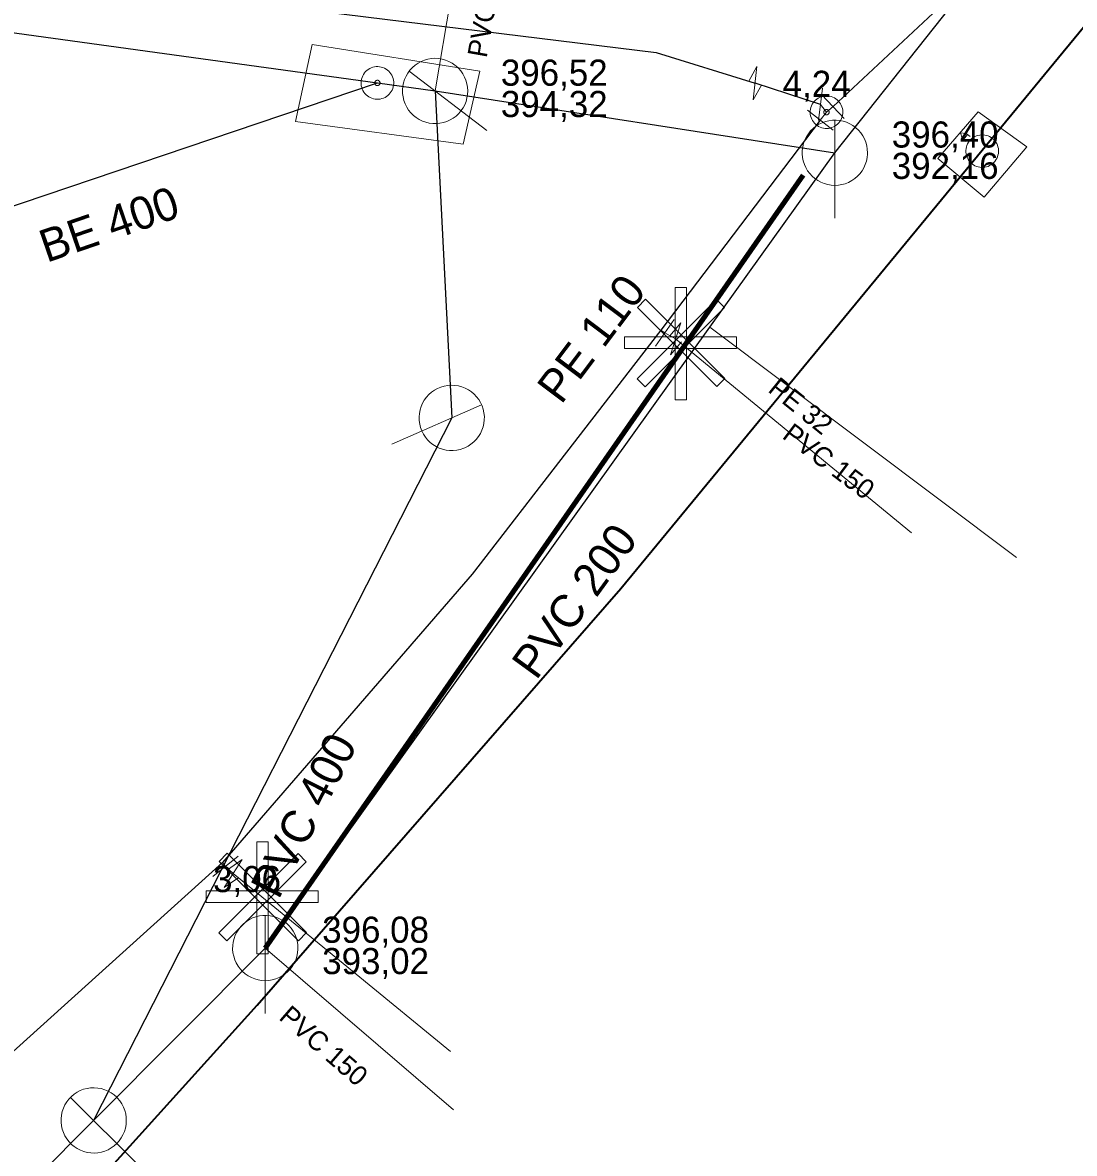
# Model space of a CAD drawing. Extents: x -809028 to -807737, y -990545 to -989489.
# Drawn here: x -808650.26 to -808618.05, y -990038.3 to -990003.67 of the extents above; entities that cross this region are included whole.
import ezdxf

# ---------------------------------------------------------------- set-up
doc = ezdxf.new("R2010")
doc.units = 0
doc.header["$LTSCALE"] = 0.32
for name, color, linetype, lineweight in [('1', 7, 'Continuous', 13), ('11', 7, 'Continuous', 13), ('12', 7, 'Continuous', 13), ('13', 7, 'Continuous', 13), ('14', 7, 'Continuous', 25), ('17', 7, 'Continuous', 25), ('2', 7, 'Continuous', 13), ('22', 7, 'Continuous', 13), ('23', 7, 'Continuous', 13), ('31', 7, 'Continuous', 13), ('34', 7, 'Continuous', 13), ('47', 7, 'Continuous', 13)]:
    doc.layers.add(name, color=color, linetype=linetype, lineweight=lineweight)

msp = doc.modelspace()

# ---------------------------------------------------------------- linework, layer by layer
at = {"layer": '1'}
msp.add_lwpolyline([(-808641.395, -990004.333), (-808641.909, -990006.699), (-808636.769, -990007.385), (-808636.254, -990005.157)], close=True, dxfattribs=at)
at = {"layer": '11'}
for p, q in [((-808636.524, -989999.172), (-808637.629, -990005.76)), ((-808619.815, -990020.044), (-808629.213, -990012.999)), ((-808637.065, -990036.969), (-808642.829, -990032.01))]:
    msp.add_line(p, q, dxfattribs=at)
at = {"layer": '12'}
for points in [[(-808630.277, -990011.784), (-808629.926, -990011.784), (-808629.926, -990015.219), (-808630.277, -990015.219)], [(-808629.011, -990012.148), (-808628.762, -990012.396), (-808631.191, -990014.825), (-808631.438, -990014.577)], [(-808631.429, -990012.387), (-808631.183, -990012.139), (-808628.754, -990014.568), (-808629, -990014.816)], [(-808628.392, -990013.293), (-808628.392, -990013.643), (-808631.828, -990013.643), (-808631.828, -990013.293)], [(-808643.093, -990028.753), (-808642.743, -990028.753), (-808642.743, -990032.188), (-808643.093, -990032.188)], [(-808641.827, -990029.117), (-808641.579, -990029.365), (-808644.008, -990031.794), (-808644.255, -990031.546)], [(-808644.246, -990029.356), (-808643.999, -990029.108), (-808641.57, -990031.537), (-808641.817, -990031.785)], [(-808641.209, -990030.262), (-808641.209, -990030.612), (-808644.644, -990030.612), (-808644.644, -990030.262)]]:
    msp.add_lwpolyline(points, close=True, dxfattribs=at)
at = {"layer": '13'}
msp.add_line((-808644.048, -990029.511), (-808643.817, -990029.732), dxfattribs=at)
for points in [[(-808630.591, -990013.17), (-808630.26, -990013.352), (-808623.037, -990019.291)], [(-808643.817, -990029.732), (-808642.936, -990030.438), (-808637.155, -990035.181)]]:
    msp.add_lwpolyline(points, dxfattribs=at)
at = {"layer": '14'}
for p, q in [((-808666.999, -990001.71), (-808639.396, -990005.515)), ((-808655.245, -990010.861), (-808639.396, -990005.515)), ((-808639.396, -990005.515), (-808637.629, -990005.76)), ((-808637.629, -990005.76), (-808637.119, -990015.773)), ((-808637.119, -990015.773), (-808648.087, -990037.289)), ((-808642.829, -990032.01), (-808648.087, -990037.289)), ((-808648.087, -990037.289), (-808655.559, -990044.789))]:
    msp.add_line(p, q, dxfattribs=at)
at = {"layer": '14', "lineweight": 13}
for p, q in [((-808625.64, -990006.41), (-808625.824, -990006.17)), ((-808625.438, -990006.24), (-808625.64, -990006.41)), ((-808625.64, -990006.41), (-808625.831, -990006.655)), ((-808630.715, -990013.083), (-808630.591, -990013.17)), ((-808644.145, -990029.39), (-808644.048, -990029.511))]:
    msp.add_line(p, q, dxfattribs=at)
at = {"layer": '14'}
for points in [[(-808637.629, -990005.76), (-808625.384, -990007.653), (-808616.276, -989996.169), (-808606.504, -989991.842)], [(-808642.829, -990032.01), (-808629.213, -990012.999), (-808625.384, -990007.653)]]:
    msp.add_lwpolyline(points, dxfattribs=at)
at = {"layer": '17'}
msp.add_line((-808625.824, -990006.17), (-808627.827, -990005.523), dxfattribs=at)
at = {"layer": '17', "lineweight": 35}
for points in [[(-808620.873, -990007.571), (-808617.482, -990003.458), (-808605.335, -989996.355), (-808589.077, -989989.493), (-808570.179, -989981.543), (-808534.115, -989966.436)], [(-808750.059, -990081.211), (-808742.603, -990078.188), (-808713.199, -990068.699), (-808700.969, -990064.837), (-808681.837, -990057.533), (-808654.215, -990046.079), (-808643.079, -990033.758), (-808631.943, -990021), (-808620.873, -990007.571)]]:
    msp.add_lwpolyline(points, dxfattribs=at)
at = {"layer": '17'}
for points in [[(-808609.716, -989992.736), (-808618.388, -989999.647), (-808625.438, -990006.24)], [(-808694.1, -989996.799), (-808693.84, -989996.838), (-808693.67, -989996.855), (-808693.169, -989996.906), (-808674.318, -989999.243), (-808671.192, -989999.618), (-808655.3, -990001.572), (-808630.859, -990004.578), (-808627.827, -990005.523)], [(-808625.831, -990006.655), (-808630.715, -990013.083), (-808636.489, -990020.561), (-808644.145, -990029.39), (-808654.25, -990038.506), (-808656.149, -990040.287), (-808660.557, -990043.436), (-808668.114, -990046.789), (-808678.127, -990051.122), (-808682.044, -990052.357), (-808691.298, -990056.515), (-808701.741, -990060.217)]]:
    msp.add_lwpolyline(points, dxfattribs=at)
at = {"layer": '2', "lineweight": 106}
msp.add_line((-808642.83, -990032.01), (-808626.352, -990008.342), dxfattribs=at)
at = {"layer": '2', "lineweight": 100}
msp.add_line((-808642.83, -990032.01), (-808626.352, -990008.342), dxfattribs=at)
at = {"layer": '2'}
msp.add_lwpolyline([(-808620.989, -990006.401), (-808622.234, -990007.824), (-808620.811, -990009.009), (-808619.508, -990007.467)], close=True, dxfattribs=at)
at = {"layer": '22'}
for p, q in [((-808636.04, -990006.975), (-808638.422, -990005.152)), ((-808625.384, -990009.653), (-808625.383, -990006.653)), ((-808638.951, -990016.575), (-808636.203, -990015.372)), ((-808642.83, -990034.01), (-808642.829, -990031.01)), ((-808646.669, -990038.7), (-808648.795, -990036.583))]:
    msp.add_line(p, q, dxfattribs=at)
for points in [[(-808637.02, -990004.966), (-808637.11, -990004.904), (-808637.207, -990004.853), (-808637.31, -990004.812), (-808637.414, -990004.783), (-808637.523, -990004.765), (-808637.632, -990004.76), (-808637.742, -990004.766), (-808637.849, -990004.785), (-808637.955, -990004.815), (-808638.056, -990004.856), (-808638.152, -990004.908), (-808638.242, -990004.971), (-808638.325, -990005.043), (-808638.399, -990005.123), (-808638.464, -990005.212), (-808638.519, -990005.306), (-808638.564, -990005.406), (-808638.597, -990005.511), (-808638.618, -990005.618), (-808638.628, -990005.726), (-808638.625, -990005.837), (-808638.611, -990005.945), (-808638.584, -990006.052), (-808638.547, -990006.154), (-808638.499, -990006.252), (-808638.439, -990006.344), (-808638.37, -990006.43), (-808638.293, -990006.507), (-808638.207, -990006.575), (-808638.114, -990006.633), (-808638.016, -990006.682), (-808637.913, -990006.718), (-808637.807, -990006.744), (-808637.698, -990006.758), (-808637.588, -990006.759), (-808637.48, -990006.749), (-808637.372, -990006.727), (-808637.268, -990006.693), (-808637.168, -990006.648), (-808637.074, -990006.592), (-808636.986, -990006.527), (-808636.906, -990006.452), (-808636.835, -990006.368), (-808636.773, -990006.278), (-808636.722, -990006.181), (-808636.681, -990006.08), (-808636.652, -990005.975), (-808636.634, -990005.866), (-808636.628, -990005.757), (-808636.634, -990005.648), (-808636.652, -990005.54), (-808636.683, -990005.434), (-808636.723, -990005.333), (-808636.776, -990005.237), (-808636.838, -990005.147), (-808636.91, -990005.064), (-808636.991, -990004.99)], [(-808624.384, -990007.653), (-808624.389, -990007.544), (-808624.407, -990007.436), (-808624.437, -990007.33), (-808624.477, -990007.229), (-808624.529, -990007.132), (-808624.591, -990007.042), (-808624.663, -990006.959), (-808624.743, -990006.885), (-808624.831, -990006.819), (-808624.925, -990006.764), (-808625.025, -990006.719), (-808625.13, -990006.686), (-808625.237, -990006.664), (-808625.346, -990006.654), (-808625.456, -990006.656), (-808625.564, -990006.67), (-808625.671, -990006.695), (-808625.774, -990006.732), (-808625.872, -990006.781), (-808625.964, -990006.839), (-808626.05, -990006.908), (-808626.127, -990006.985), (-808626.196, -990007.071), (-808626.255, -990007.163), (-808626.303, -990007.261), (-808626.34, -990007.364), (-808626.366, -990007.471), (-808626.38, -990007.579), (-808626.383, -990007.689), (-808626.373, -990007.798), (-808626.352, -990007.905), (-808626.318, -990008.009), (-808626.274, -990008.109), (-808626.219, -990008.204), (-808626.153, -990008.292), (-808626.079, -990008.372), (-808625.996, -990008.444), (-808625.906, -990008.506), (-808625.81, -990008.558), (-808625.708, -990008.599), (-808625.603, -990008.629), (-808625.495, -990008.647), (-808625.385, -990008.653), (-808625.276, -990008.647), (-808625.168, -990008.629), (-808625.063, -990008.6), (-808624.961, -990008.559), (-808624.864, -990008.507), (-808624.774, -990008.445), (-808624.691, -990008.374), (-808624.616, -990008.294), (-808624.551, -990008.206), (-808624.495, -990008.112), (-808624.451, -990008.012), (-808624.417, -990007.908), (-808624.395, -990007.8), (-808624.385, -990007.691)], [(-808636.718, -990016.689), (-808636.62, -990016.64), (-808636.529, -990016.58), (-808636.444, -990016.51), (-808636.367, -990016.433), (-808636.299, -990016.346), (-808636.242, -990016.253), (-808636.194, -990016.154), (-808636.159, -990016.051), (-808636.134, -990015.944), (-808636.121, -990015.836), (-808636.12, -990015.726), (-808636.132, -990015.617), (-808636.154, -990015.51), (-808636.189, -990015.406), (-808636.235, -990015.306), (-808636.291, -990015.213), (-808636.357, -990015.125), (-808636.432, -990015.045), (-808636.516, -990014.975), (-808636.606, -990014.914), (-808636.704, -990014.863), (-808636.805, -990014.823), (-808636.912, -990014.795), (-808637.02, -990014.777), (-808637.129, -990014.773), (-808637.238, -990014.78), (-808637.346, -990014.799), (-808637.451, -990014.83), (-808637.553, -990014.872), (-808637.648, -990014.925), (-808637.738, -990014.987), (-808637.82, -990015.06), (-808637.894, -990015.14), (-808637.959, -990015.229), (-808638.013, -990015.325), (-808638.056, -990015.424), (-808638.089, -990015.529), (-808638.11, -990015.637), (-808638.119, -990015.745), (-808638.115, -990015.855), (-808638.101, -990015.964), (-808638.074, -990016.07), (-808638.035, -990016.173), (-808637.986, -990016.27), (-808637.926, -990016.362), (-808637.858, -990016.447), (-808637.779, -990016.524), (-808637.693, -990016.592), (-808637.6, -990016.649), (-808637.502, -990016.697), (-808637.398, -990016.733), (-808637.291, -990016.758), (-808637.183, -990016.771), (-808637.074, -990016.771), (-808636.965, -990016.761), (-808636.857, -990016.738), (-808636.753, -990016.703)], [(-808641.83, -990032.01), (-808641.835, -990031.901), (-808641.853, -990031.793), (-808641.883, -990031.687), (-808641.923, -990031.586), (-808641.975, -990031.489), (-808642.037, -990031.399), (-808642.109, -990031.316), (-808642.189, -990031.242), (-808642.277, -990031.176), (-808642.371, -990031.121), (-808642.471, -990031.076), (-808642.576, -990031.043), (-808642.683, -990031.021), (-808642.792, -990031.011), (-808642.902, -990031.013), (-808643.01, -990031.027), (-808643.117, -990031.052), (-808643.22, -990031.089), (-808643.318, -990031.138), (-808643.41, -990031.196), (-808643.496, -990031.265), (-808643.573, -990031.342), (-808643.642, -990031.428), (-808643.701, -990031.52), (-808643.749, -990031.618), (-808643.786, -990031.721), (-808643.812, -990031.828), (-808643.826, -990031.936), (-808643.829, -990032.046), (-808643.819, -990032.155), (-808643.798, -990032.262), (-808643.764, -990032.366), (-808643.72, -990032.466), (-808643.665, -990032.561), (-808643.599, -990032.649), (-808643.525, -990032.729), (-808643.442, -990032.801), (-808643.352, -990032.863), (-808643.256, -990032.915), (-808643.154, -990032.956), (-808643.049, -990032.986), (-808642.941, -990033.004), (-808642.831, -990033.01), (-808642.722, -990033.004), (-808642.614, -990032.986), (-808642.509, -990032.957), (-808642.407, -990032.916), (-808642.31, -990032.864), (-808642.22, -990032.802), (-808642.137, -990032.731), (-808642.062, -990032.651), (-808641.997, -990032.563), (-808641.941, -990032.469), (-808641.897, -990032.369), (-808641.863, -990032.265), (-808641.841, -990032.157), (-808641.831, -990032.048)], [(-808647.38, -990036.58), (-808647.462, -990036.508), (-808647.551, -990036.444), (-808647.647, -990036.391), (-808647.747, -990036.348), (-808647.853, -990036.316), (-808647.96, -990036.297), (-808648.07, -990036.289), (-808648.179, -990036.293), (-808648.287, -990036.309), (-808648.393, -990036.337), (-808648.495, -990036.376), (-808648.593, -990036.427), (-808648.684, -990036.487), (-808648.768, -990036.558), (-808648.844, -990036.637), (-808648.91, -990036.723), (-808648.968, -990036.817), (-808649.015, -990036.916), (-808649.049, -990037.02), (-808649.073, -990037.126), (-808649.085, -990037.236), (-808649.084, -990037.345), (-808649.072, -990037.454), (-808649.049, -990037.561), (-808649.013, -990037.664), (-808648.966, -990037.763), (-808648.909, -990037.857), (-808648.842, -990037.943), (-808648.766, -990038.022), (-808648.681, -990038.092), (-808648.591, -990038.153), (-808648.493, -990038.202), (-808648.391, -990038.241), (-808648.285, -990038.269), (-808648.176, -990038.285), (-808648.067, -990038.289), (-808647.958, -990038.281), (-808647.85, -990038.261), (-808647.746, -990038.229), (-808647.645, -990038.186), (-808647.549, -990038.133), (-808647.46, -990038.069), (-808647.378, -990037.995), (-808647.306, -990037.914), (-808647.242, -990037.825), (-808647.189, -990037.73), (-808647.146, -990037.629), (-808647.114, -990037.523), (-808647.095, -990037.416), (-808647.086, -990037.307), (-808647.09, -990037.197), (-808647.106, -990037.089), (-808647.134, -990036.983), (-808647.173, -990036.881), (-808647.223, -990036.784), (-808647.284, -990036.692), (-808647.354, -990036.608)]]:
    msp.add_lwpolyline(points, close=True, dxfattribs=at)
at = {"layer": '23'}
msp.add_line((-808621.317, -990007.092), (-808621.442, -990007.243), dxfattribs=at)
for points in [[(-808621.367, -990007.305), (-808621.482, -990007.21), (-808621.536, -990007.038), (-808621.358, -990007.059), (-808621.243, -990007.154)], [(-808620.556, -990007.214), (-808620.598, -990007.182), (-808620.644, -990007.156), (-808620.692, -990007.136), (-808620.741, -990007.12), (-808620.792, -990007.109), (-808620.845, -990007.104), (-808620.897, -990007.104), (-808620.948, -990007.11), (-808621, -990007.121), (-808621.05, -990007.137), (-808621.098, -990007.158), (-808621.144, -990007.185), (-808621.186, -990007.215), (-808621.223, -990007.25), (-808621.259, -990007.288), (-808621.29, -990007.333), (-808621.316, -990007.376), (-808621.337, -990007.426), (-808621.353, -990007.474), (-808621.365, -990007.525), (-808621.369, -990007.579), (-808621.369, -990007.631), (-808621.363, -990007.683), (-808621.353, -990007.734), (-808621.336, -990007.783), (-808621.314, -990007.831), (-808621.288, -990007.876), (-808621.257, -990007.918), (-808621.221, -990007.957), (-808621.183, -990007.992), (-808621.141, -990008.023), (-808621.095, -990008.049), (-808621.047, -990008.071), (-808620.998, -990008.087), (-808620.947, -990008.096), (-808620.895, -990008.102), (-808620.842, -990008.102), (-808620.79, -990008.096), (-808620.739, -990008.085)], [(-808621.337, -990007.426), (-808621.353, -990007.474), (-808621.365, -990007.525), (-808621.369, -990007.579), (-808621.369, -990007.631), (-808621.363, -990007.683), (-808621.353, -990007.734), (-808621.336, -990007.783), (-808621.314, -990007.831), (-808621.288, -990007.876), (-808621.257, -990007.918), (-808621.221, -990007.957), (-808621.183, -990007.992), (-808621.141, -990008.023), (-808621.095, -990008.049), (-808621.047, -990008.071), (-808620.998, -990008.087), (-808620.947, -990008.096), (-808620.895, -990008.102), (-808620.842, -990008.102), (-808620.79, -990008.096), (-808620.739, -990008.085), (-808620.69, -990008.07), (-808620.642, -990008.047), (-808620.596, -990008.022), (-808620.554, -990007.99), (-808620.516, -990007.955), (-808620.481, -990007.917), (-808620.451, -990007.874), (-808620.424, -990007.829), (-808620.402, -990007.781), (-808620.387, -990007.731), (-808620.376, -990007.679), (-808620.37, -990007.628), (-808620.372, -990007.575), (-808620.376, -990007.524), (-808620.387, -990007.473), (-808620.403, -990007.422), (-808620.425, -990007.374), (-808620.451, -990007.329)], [(-808620.739, -990008.085), (-808620.69, -990008.07), (-808620.642, -990008.047), (-808620.596, -990008.022), (-808620.554, -990007.99), (-808620.516, -990007.955), (-808620.481, -990007.917), (-808620.451, -990007.874), (-808620.424, -990007.829), (-808620.402, -990007.781), (-808620.387, -990007.731), (-808620.376, -990007.679), (-808620.37, -990007.628), (-808620.372, -990007.575), (-808620.376, -990007.524), (-808620.387, -990007.473), (-808620.403, -990007.422), (-808620.425, -990007.374), (-808620.451, -990007.329), (-808620.483, -990007.288), (-808620.517, -990007.249), (-808620.556, -990007.214), (-808620.598, -990007.182), (-808620.644, -990007.156), (-808620.692, -990007.136), (-808620.741, -990007.12), (-808620.792, -990007.109), (-808620.845, -990007.104), (-808620.897, -990007.104), (-808620.948, -990007.11), (-808621, -990007.121), (-808621.05, -990007.137), (-808621.098, -990007.158), (-808621.144, -990007.185), (-808621.186, -990007.215), (-808621.223, -990007.25), (-808621.259, -990007.288), (-808621.29, -990007.333), (-808621.316, -990007.376), (-808621.337, -990007.426)], [(-808620.451, -990007.329), (-808620.483, -990007.288), (-808620.517, -990007.249), (-808620.556, -990007.214)]]:
    msp.add_lwpolyline(points, dxfattribs=at)
at = {"layer": '31'}
for points in [[(-808638.9, -990005.583), (-808638.896, -990005.531), (-808638.897, -990005.478), (-808638.904, -990005.427), (-808638.915, -990005.376), (-808638.932, -990005.326), (-808638.955, -990005.278), (-808638.982, -990005.234), (-808639.014, -990005.193), (-808639.049, -990005.154), (-808639.089, -990005.12), (-808639.132, -990005.09), (-808639.178, -990005.065), (-808639.226, -990005.044), (-808639.276, -990005.029), (-808639.327, -990005.019), (-808639.379, -990005.015), (-808639.432, -990005.016), (-808639.484, -990005.023), (-808639.534, -990005.034), (-808639.584, -990005.051), (-808639.632, -990005.074), (-808639.677, -990005.101), (-808639.718, -990005.133), (-808639.757, -990005.168), (-808639.79, -990005.208), (-808639.82, -990005.251), (-808639.846, -990005.297), (-808639.866, -990005.345), (-808639.881, -990005.395), (-808639.891, -990005.446), (-808639.895, -990005.498), (-808639.894, -990005.551), (-808639.888, -990005.603), (-808639.876, -990005.653), (-808639.859, -990005.703), (-808639.837, -990005.75), (-808639.81, -990005.796), (-808639.778, -990005.837), (-808639.742, -990005.876), (-808639.702, -990005.909), (-808639.659, -990005.939), (-808639.614, -990005.965), (-808639.565, -990005.985), (-808639.515, -990006), (-808639.464, -990006.01), (-808639.412, -990006.014), (-808639.359, -990006.013), (-808639.308, -990006.007), (-808639.257, -990005.995), (-808639.207, -990005.978), (-808639.16, -990005.956), (-808639.115, -990005.929), (-808639.074, -990005.897), (-808639.035, -990005.861), (-808639.001, -990005.821), (-808638.971, -990005.778), (-808638.946, -990005.733), (-808638.925, -990005.684), (-808638.91, -990005.634)], [(-808639.314, -990005.526), (-808639.313, -990005.517), (-808639.314, -990005.509), (-808639.315, -990005.5), (-808639.317, -990005.492), (-808639.32, -990005.484), (-808639.324, -990005.476), (-808639.328, -990005.468), (-808639.333, -990005.462), (-808639.339, -990005.456), (-808639.345, -990005.45), (-808639.353, -990005.445), (-808639.36, -990005.441), (-808639.368, -990005.438), (-808639.375, -990005.434), (-808639.384, -990005.433), (-808639.393, -990005.432), (-808639.401, -990005.433), (-808639.41, -990005.434), (-808639.418, -990005.436), (-808639.426, -990005.439), (-808639.434, -990005.443), (-808639.442, -990005.447), (-808639.448, -990005.452), (-808639.455, -990005.458), (-808639.46, -990005.464), (-808639.465, -990005.472), (-808639.469, -990005.479), (-808639.472, -990005.487), (-808639.476, -990005.494), (-808639.477, -990005.503), (-808639.478, -990005.512), (-808639.477, -990005.52), (-808639.476, -990005.529), (-808639.474, -990005.537), (-808639.471, -990005.545), (-808639.468, -990005.553), (-808639.463, -990005.561), (-808639.458, -990005.567), (-808639.452, -990005.574), (-808639.446, -990005.579), (-808639.438, -990005.584), (-808639.431, -990005.588), (-808639.423, -990005.591), (-808639.416, -990005.595), (-808639.407, -990005.596), (-808639.398, -990005.597), (-808639.39, -990005.596), (-808639.381, -990005.595), (-808639.373, -990005.593), (-808639.365, -990005.59), (-808639.357, -990005.587), (-808639.349, -990005.582), (-808639.343, -990005.577), (-808639.337, -990005.571), (-808639.331, -990005.565), (-808639.326, -990005.557), (-808639.322, -990005.55), (-808639.319, -990005.542), (-808639.315, -990005.535)]]:
    msp.add_lwpolyline(points, close=True, dxfattribs=at)
at = {"layer": '34'}
for p, q in [((-808625.763, -990005.673), (-808625.885, -990006.666)), ((-808625.779, -990005.875), (-808625.096, -990006.605)), ((-808626.226, -990006.348), (-808625.436, -990006.961)), ((-808630.302, -990012.761), (-808630.88, -990013.577)), ((-808643.658, -990029.197), (-808644.438, -990029.823))]:
    msp.add_line(p, q, dxfattribs=at)
at = {"layer": '47'}
for p, q in [((-808627.771, -990005.016), (-808628.018, -990005.463)), ((-808630.104, -990012.866), (-808630.436, -990013.255)), ((-808643.541, -990029.303), (-808643.961, -990029.592))]:
    msp.add_line(p, q, dxfattribs=at)
for points in [[(-808627.771, -990005.016), (-808627.882, -990006.029), (-808627.635, -990005.582)], [(-808630.104, -990012.866), (-808630.415, -990013.837), (-808630.083, -990013.448)], [(-808643.541, -990029.303), (-808644.092, -990030.16), (-808643.672, -990029.871)]]:
    msp.add_lwpolyline(points, dxfattribs=at)
for points in [[(-808625.274, -990006.069), (-808625.311, -990006.033), (-808625.353, -990006), (-808625.397, -990005.973), (-808625.444, -990005.949), (-808625.493, -990005.931), (-808625.545, -990005.919), (-808625.596, -990005.912), (-808625.648, -990005.91), (-808625.7, -990005.914), (-808625.752, -990005.922), (-808625.803, -990005.937), (-808625.851, -990005.957), (-808625.897, -990005.981), (-808625.94, -990006.011), (-808625.98, -990006.044), (-808626.016, -990006.081), (-808626.049, -990006.123), (-808626.077, -990006.168), (-808626.1, -990006.214), (-808626.118, -990006.263), (-808626.13, -990006.315), (-808626.138, -990006.367), (-808626.139, -990006.419), (-808626.136, -990006.471), (-808626.127, -990006.522), (-808626.112, -990006.573), (-808626.093, -990006.621), (-808626.068, -990006.667), (-808626.038, -990006.71), (-808626.005, -990006.75), (-808625.968, -990006.786), (-808625.926, -990006.819), (-808625.882, -990006.847), (-808625.835, -990006.87), (-808625.786, -990006.888), (-808625.735, -990006.901), (-808625.683, -990006.908), (-808625.631, -990006.91), (-808625.578, -990006.906), (-808625.527, -990006.897), (-808625.476, -990006.882), (-808625.428, -990006.863), (-808625.382, -990006.838), (-808625.339, -990006.808), (-808625.299, -990006.775), (-808625.263, -990006.738), (-808625.23, -990006.696), (-808625.202, -990006.653), (-808625.179, -990006.605), (-808625.161, -990006.556), (-808625.148, -990006.505), (-808625.142, -990006.454), (-808625.14, -990006.401), (-808625.144, -990006.349), (-808625.152, -990006.297), (-808625.167, -990006.246), (-808625.186, -990006.199), (-808625.211, -990006.152), (-808625.241, -990006.109)], [(-808625.58, -990006.354), (-808625.586, -990006.347), (-808625.593, -990006.343), (-808625.6, -990006.338), (-808625.607, -990006.334), (-808625.616, -990006.331), (-808625.624, -990006.329), (-808625.632, -990006.328), (-808625.641, -990006.327), (-808625.649, -990006.328), (-808625.658, -990006.33), (-808625.667, -990006.332), (-808625.674, -990006.335), (-808625.682, -990006.339), (-808625.689, -990006.343), (-808625.695, -990006.35), (-808625.702, -990006.356), (-808625.706, -990006.363), (-808625.711, -990006.37), (-808625.715, -990006.377), (-808625.718, -990006.386), (-808625.72, -990006.394), (-808625.721, -990006.402), (-808625.722, -990006.411), (-808625.721, -990006.42), (-808625.719, -990006.428), (-808625.717, -990006.437), (-808625.714, -990006.444), (-808625.71, -990006.452), (-808625.706, -990006.459), (-808625.699, -990006.465), (-808625.693, -990006.472), (-808625.686, -990006.476), (-808625.679, -990006.481), (-808625.672, -990006.485), (-808625.663, -990006.488), (-808625.656, -990006.49), (-808625.647, -990006.491), (-808625.638, -990006.492), (-808625.629, -990006.491), (-808625.621, -990006.489), (-808625.612, -990006.487), (-808625.605, -990006.484), (-808625.597, -990006.48), (-808625.59, -990006.476), (-808625.584, -990006.469), (-808625.577, -990006.463), (-808625.573, -990006.456), (-808625.568, -990006.449), (-808625.564, -990006.442), (-808625.561, -990006.433), (-808625.559, -990006.426), (-808625.558, -990006.417), (-808625.557, -990006.408), (-808625.558, -990006.4), (-808625.56, -990006.391), (-808625.562, -990006.382), (-808625.565, -990006.375), (-808625.569, -990006.367), (-808625.573, -990006.36)]]:
    msp.add_lwpolyline(points, close=True, dxfattribs=at)

# ---------------------------------------------------------------- texts
at = {"layer": '1'}
for s, height, rotation, p in [('PVC 150 ', 0.6, 80, (-808636.051, -990004.766)), ('BE 400', 1, 19, (-808649.528, -990011.027)), ('PE 110', 1, 53, (-808633.767, -990015.39)), ('PE 32 ', 0.6, 321, (-808627.464, -990014.95)), ('PVC 150 ', 0.6, 323, (-808627.028, -990016.375)), ('PVC 200 ', 1, 54, (-808634.53, -990023.832)), ('PVC 400 ', 1, 63, (-808642.424, -990030.55)), ('PVC 150 ', 0.6, 319, (-808642.446, -990034.174))]:
    msp.add_text(s, height=height, rotation=rotation, dxfattribs=at).set_placement(p)
for s, p in [('4,24', (-808626.983, -990005.942)), ('3,06', (-808644.43, -990030.298))]:
    msp.add_text(s, height=0.8, dxfattribs=at).set_placement(p)
at = {"layer": '14'}
for s, p in [('396,52', (-808635.615, -990005.599)), ('394,32', (-808635.615, -990006.559)), ('396,40', (-808623.641, -990007.494)), ('392,16', (-808623.641, -990008.454)), ('396,08', (-808641.087, -990031.849)), ('393,02', (-808641.087, -990032.809))]:
    msp.add_text(s, height=0.8, dxfattribs=at).set_placement(p)

doc.saveas('drawing.dxf')
